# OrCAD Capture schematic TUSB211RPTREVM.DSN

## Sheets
1 PAGE3: size C; title: TUSB211RPTREVM; rev: B; note: 6582632
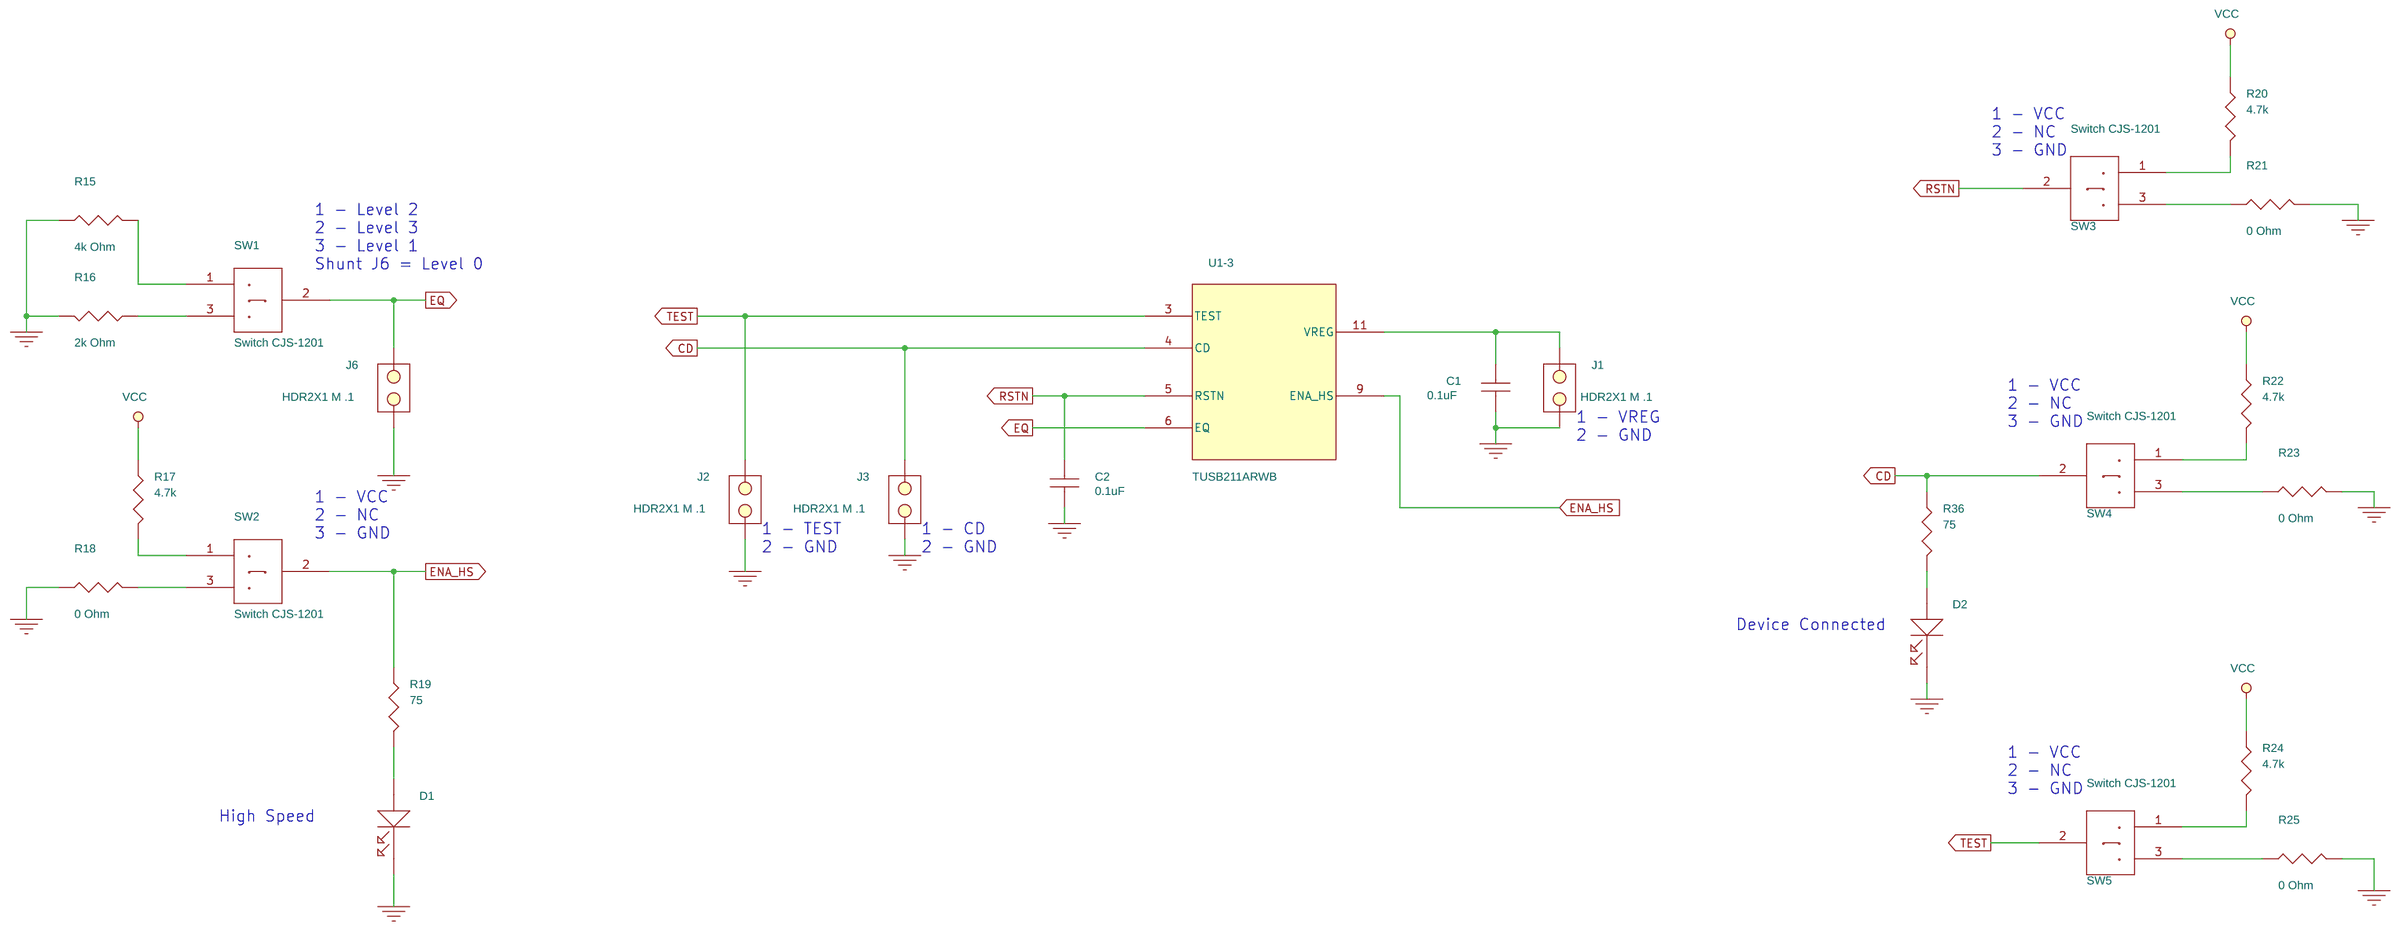
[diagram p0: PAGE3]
2 PAGE2: size C
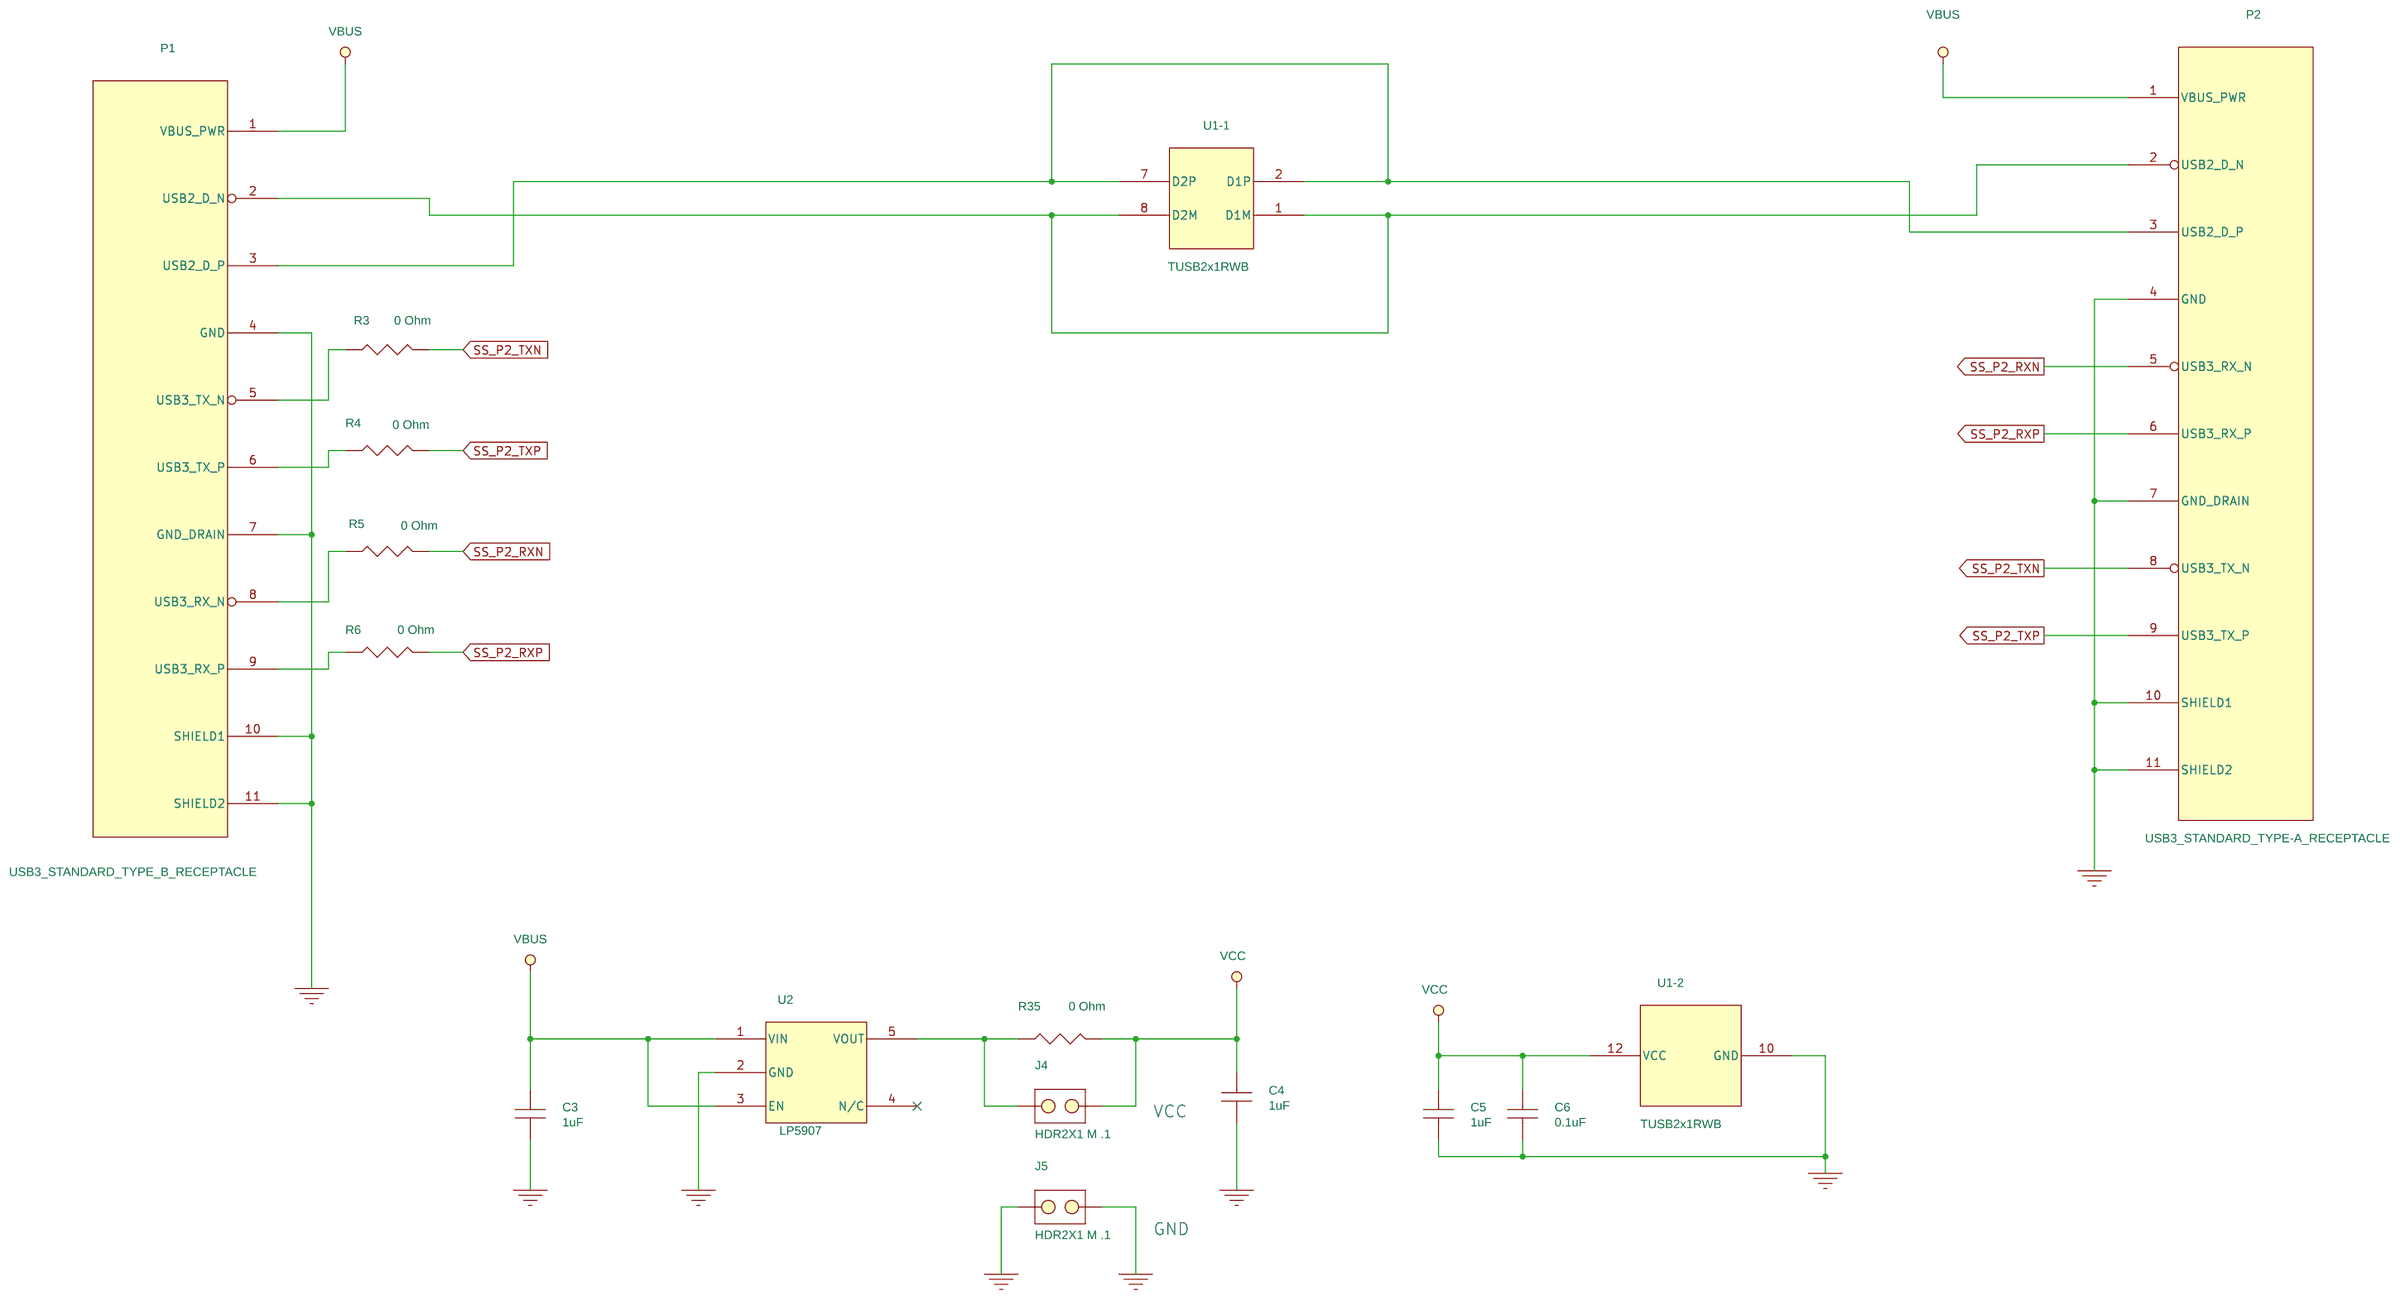
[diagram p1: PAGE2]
3 PAGE1
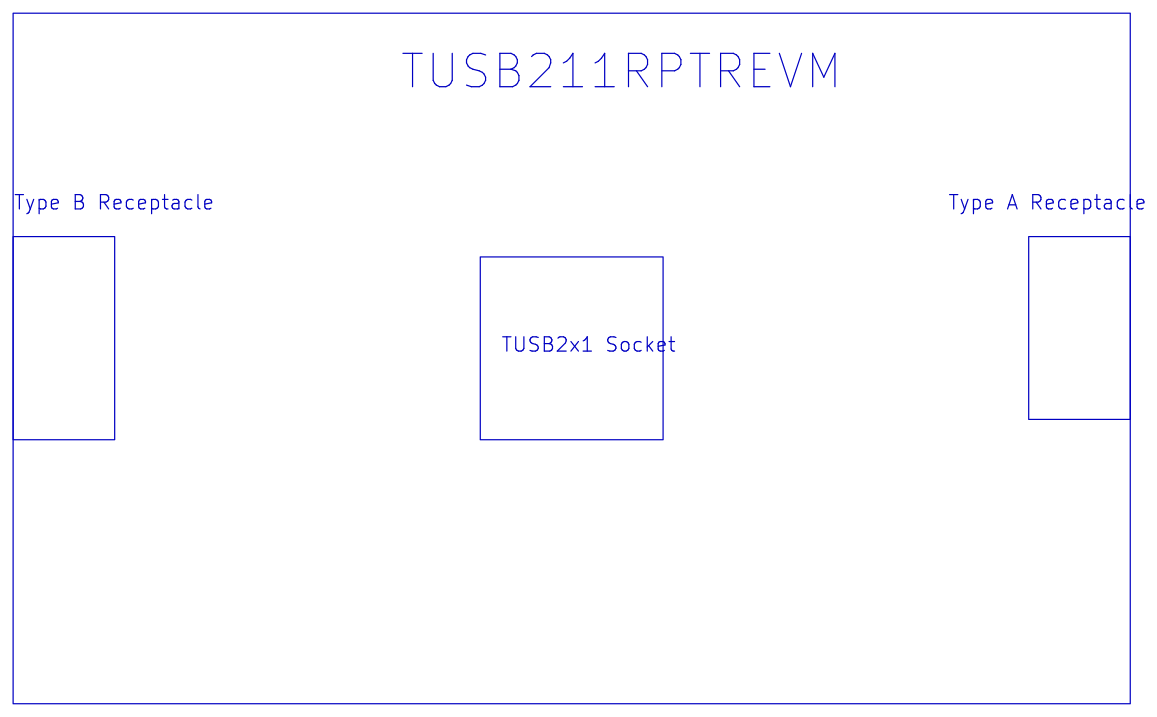
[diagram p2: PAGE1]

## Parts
sheet PAGE2
C3  1uF  [0603]
C4  1uF  [0603]
C5  1uF  [0201]
C6  0.1uF  [0201]
J4  HDR2X1 M .1  [CON_THVT_1x2_100_M]
J5  HDR2X1 M .1  [CON_THVT_1x2_100_M]
P1  USB3_STANDARD_TYPE_B_RECEPTACLE  [usb3_typeb_ak4aa009]
P2  USB3_STANDARD_TYPE-A_RECEPTACLE  [USB3_TYPEA]
R3  0 Ohm  [0201]
R4  0 Ohm  [0201]
R5  0 Ohm  [0201]
R6  0 Ohm  [0201]
R35  0 Ohm  [0603]
U1  TUSB2x1RWB  [ironwood_12pin_c13115]  (sections -1,-2,-3)
U2  LP5907  [DBV_R-PDSO-G5]
sheet PAGE3
C1  0.1uF  [0402]
C2  0.1uF  [0201]
D1  LED  [0805]
D2  LED  [cc0805]
J1  HDR2X1 M .1  [CON_THVT_1x2_100_M]
J2  HDR2X1 M .1  [CON_THVT_1x2_100_M]
J3  HDR2X1 M .1  [CON_THVT_1x2_100_M]
J6  HDR2X1 M .1  [CON_THVT_1x2_100_M]
R15  4k Ohm  [0402]
R16  2k Ohm  [0402]
R17  4.7k  [0402]
R18  0 Ohm  [0402]
R19  75  [0402]
R20  4.7k  [0402]
R21  0 Ohm  [0402]
R22  4.7k  [0402]
R23  0 Ohm  [0402]
R24  4.7k  [0402]
R25  0 Ohm  [0402]
R36  75  [0402]
SW1  Switch CJS-1201  [cjs-1200b]
SW2  Switch CJS-1201  [cjs-1200b]
SW3  Switch CJS-1201  [cjs-1200b]
SW4  Switch CJS-1201  [cjs-1200b]
SW5  Switch CJS-1201  [cjs-1200b]

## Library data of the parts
C3-C5 = cc0603
C1 C2 C6 = cc0402
J1-J6 = HDR2X1_M_.1
P1 = USB3_STANDARD_TYPE_B_RECEPTACLE
P2 = USB3_STANDARD_TYPE-A_RECEPTACLE
R3-R6 = r0201
R35 = r0603
U1 = TUSB2x1RWB_0: Color: Default; Location X-Coordinate: 0; Location Y-Coordinate: 0; Power Pins Visible: False; Primitive: DEFAULT
U2 = LP5907
D1 = d0805_Green
D2 = d0805_Yellow
R15-R25 R36 = r0402
SW1-SW5 = Switch_CJS-1201

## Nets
GND: C1.2 C2.2 C3.2 C4.2 C5.2 C6.2 D1.1 D2.1 J1.2 J2.2 J3.2 J5.1 J5.2 J6.2 P1.4(GND) P1.7(GND_DRAIN) P1.10(SHIELD1) P1.11(SHIELD2) P2.4(GND) P2.7(GND_DRAIN) P2.10(SHIELD1) P2.11(SHIELD2) R15.1 R16.2 R18.1 R21.2 R23.2 R25.2 U1.10(GND) U2.2(GND)
VBUS: C3.1 P1.1(VBUS_PWR) P2.1(VBUS_PWR) U2.1(VIN) U2.3(EN)
VCC: C4.1 C5.1 C6.1 J4.2 R17.1 R20.1 R22.1 R24.1 R35.2 U1.12(VCC)
CD: J3.1 R36.1 SW4.2 U1.4(CD)
ENA_HS: R19.1 SW2.2 U1.9(ENA_HS)
EQ: J6.1 SW1.2 U1.6(EQ)
RSTN: C2.1 SW3.2 U1.5(RSTN)
SS_P2_RXN: P2.5(USB3_RX_N) R5.2
SS_P2_RXP: P2.6(USB3_RX_P) R6.2
SS_P2_TXN: P2.8(USB3_TX_N) R3.2
SS_P2_TXP: P2.9(USB3_TX_P) R4.2
TEST: J2.1 SW5.2 U1.3(TEST)
N16594201: P1.3(USB2_D_P) P2.3(USB2_D_P) U1.2(D1P) U1.7(D2P)
N16594205: P1.2(USB2_D_N) P2.2(USB2_D_N) U1.1(D1M) U1.8(D2M)
N16594567: P1.5(USB3_TX_N) R3.1
N16594571: P1.6(USB3_TX_P) R4.1
N16594575: P1.8(USB3_RX_N) R5.1
N16594579: P1.9(USB3_RX_P) R6.1
N16603335: R15.2 SW1.1
N16603355: R16.1 SW1.3
N16603371: R17.2 SW2.1
N16603379: R18.2 SW2.3
N16603391: R20.2 SW3.1
N16603403: R21.1 SW3.3
N16603419: R22.2 SW4.1
N16603427: R23.1 SW4.3
N16603439: R24.2 SW5.1
N16603451: R25.1 SW5.3
N16603507: D1.2 R19.2
N16603717: C1.1 J1.1 U1.11(VREG)
N16608838: J4.1 R35.1 U2.5(VOUT)
N16618316: D2.2 R36.2

Not connected (* = marked no-connect by the designer): U2 4(N/C)*

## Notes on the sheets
sheet 1
- 1 - VCC
  2 - NC
  3 - GND
- 1 - Level 2
  2 - Level 3
  3 - Level 1
  Shunt J6 = Level 0
- 1 - VCC
  2 - NC
  3 - GND
- 1 - VREG
  2 - GND
- 1 - VCC
  2 - NC
  3 - GND
- 1 - TEST
  2 - GND
- 1 - CD
  2 - GND
- Device Connected
- 1 - VCC
  2 - NC
  3 - GND
- High Speed
sheet 2
- VCC
- GND
sheet 3
- TUSB211RPTREVM
- Type B Receptacle
- Type A Receptacle
- TUSB2x1 Socket
